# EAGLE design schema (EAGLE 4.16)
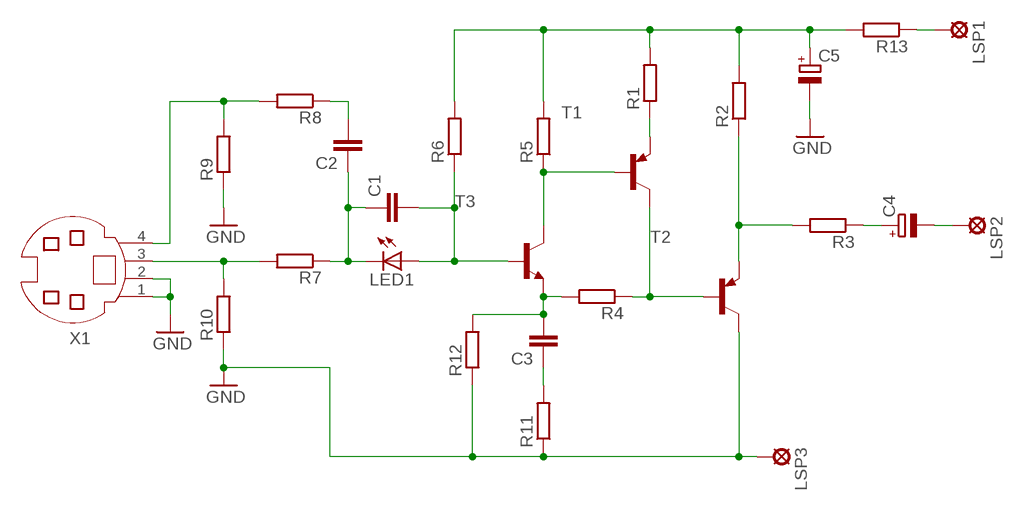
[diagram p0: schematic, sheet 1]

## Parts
C1  C-EU025-030X050  [C025-030X050]
C2  C-EU025-030X050  [C025-030X050]
C3  C-EU025-030X050  [C025-030X050]
C4  CPOL-EUSANYO_C  [SANYO-OSCON_C]
C5  CPOL-EUSANYO_C  [SANYO-OSCON_C]
LED1  LED5MM  [LED5MM]
LSP1  LSP11  [LSP11]
LSP2  LSP11  [LSP11]
LSP3  LSP11  [LSP11]
R1  R-EU_0204/7  [0204/7]
R2  R-EU_0204/7  [0204/7]
R3  R-EU_0204/7  [0204/7]
R4  R-EU_0204/7  [0204/7]
R5  R-EU_0204/7  [0204/7]
R6  R-EU_0204/7  [0204/7]
R7  R-EU_0204/7  [0204/7]
R8  R-EU_0204/7  [0204/7]
R9  R-EU_0204/7  [0204/7]
R10  R-EU_0204/7  [0204/7]
R11  R-EU_0204/7  [0204/7]
R12  R-EU_0204/7  [0204/7]
R13  R-EU_0204/7  [0204/7]
T1  BF421-PNP-TO92-BCE  [TO92-BCE]
T2  BF421-PNP-TO92-BCE  [TO92-BCE]
T3  BF199-NPN-TO92-BEC  [TO92-BEC]
X1  MD04S  [MDIN04S]

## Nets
GND: C5.- LSP3.MP R9.1 R10.1 R11.1 R12.1 T2.C X1.1 X1.2
N$1: R4.1 T1.C T2.B
N$2: R1.1 T1.E
N$3: R2.1 R3.2 T2.E
N$4: C3.2 R4.2 R12.2 T3.E
N$5: R5.1 T1.B T3.C
N$6: C5.+ R1.2 R2.2 R5.2 R6.2 R13.2
N$8: C1.2 LED1.A R6.1 T3.B
N$9: C1.1 C2.1 LED1.K(C) R7.1
N$10: C2.2 R8.1
N$11: R7.2 R10.2 X1.3
N$12: R8.2 R9.2 X1.4
N$13: C3.1 R11.2
N$16: C4.+ R3.1
N$17: LSP1.MP R13.1
N$18: C4.- LSP2.MP

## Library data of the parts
C1-C3 = rcl:C-EU: CAPACITOR, European symbol
C4 C5 = rcl:CPOL-EU: POLARIZED CAPACITOR, European symbol
LED1 = led:LED: LED
LSP1-LSP3 = solpad:LSP11: SOLDER PAD
R1-R13 = rcl:R-EU_: RESISTOR, European symbol
T1 T2 = transistor:*-PNP-: PNP Transistror
T3 = transistor:*-NPN-: NPN Transistror
X1 = con-yamaichi:MD04S: YAMAICHI CONNECTOR

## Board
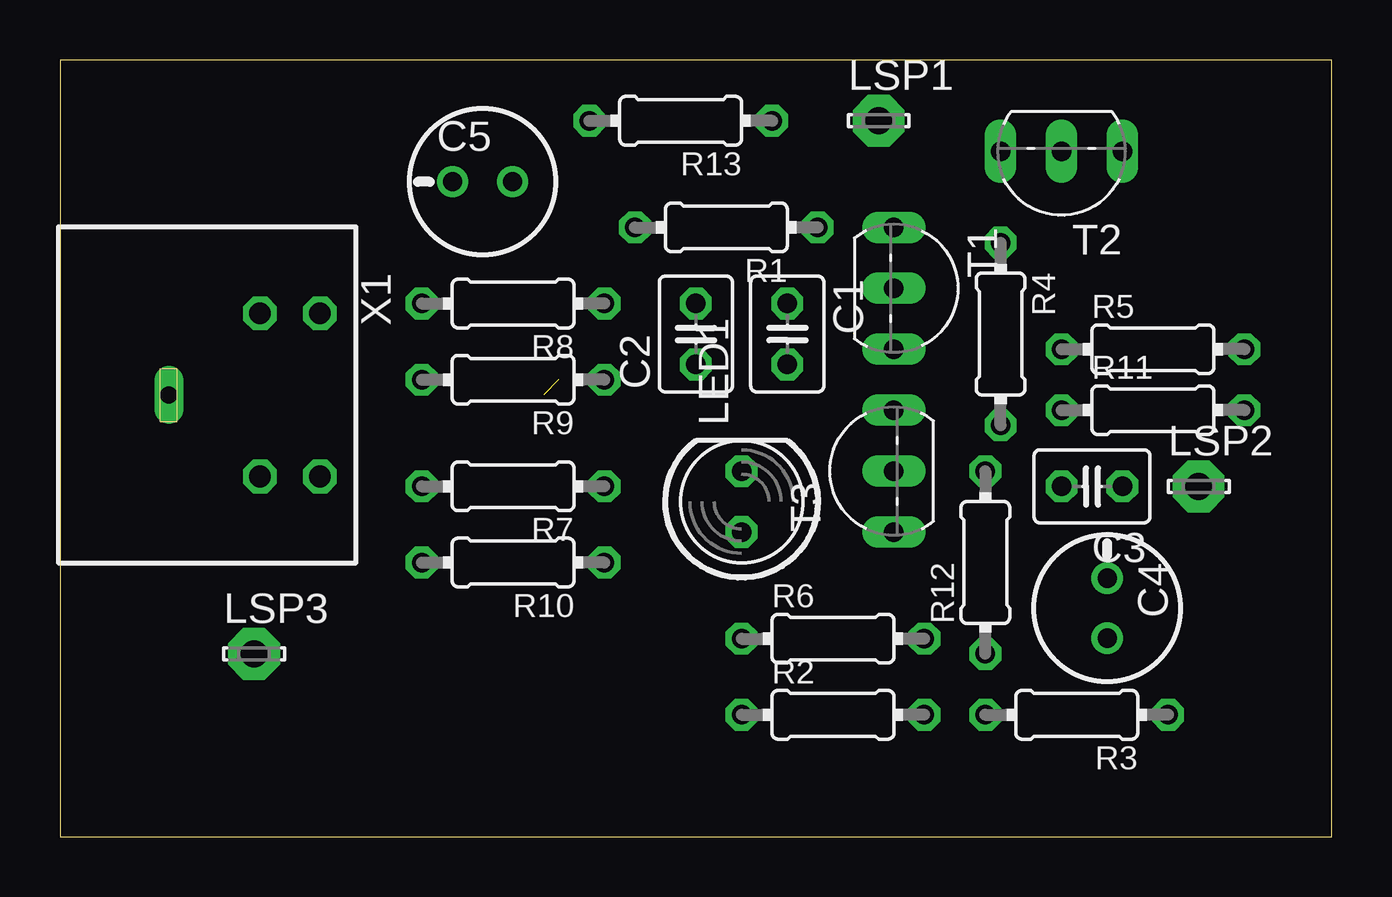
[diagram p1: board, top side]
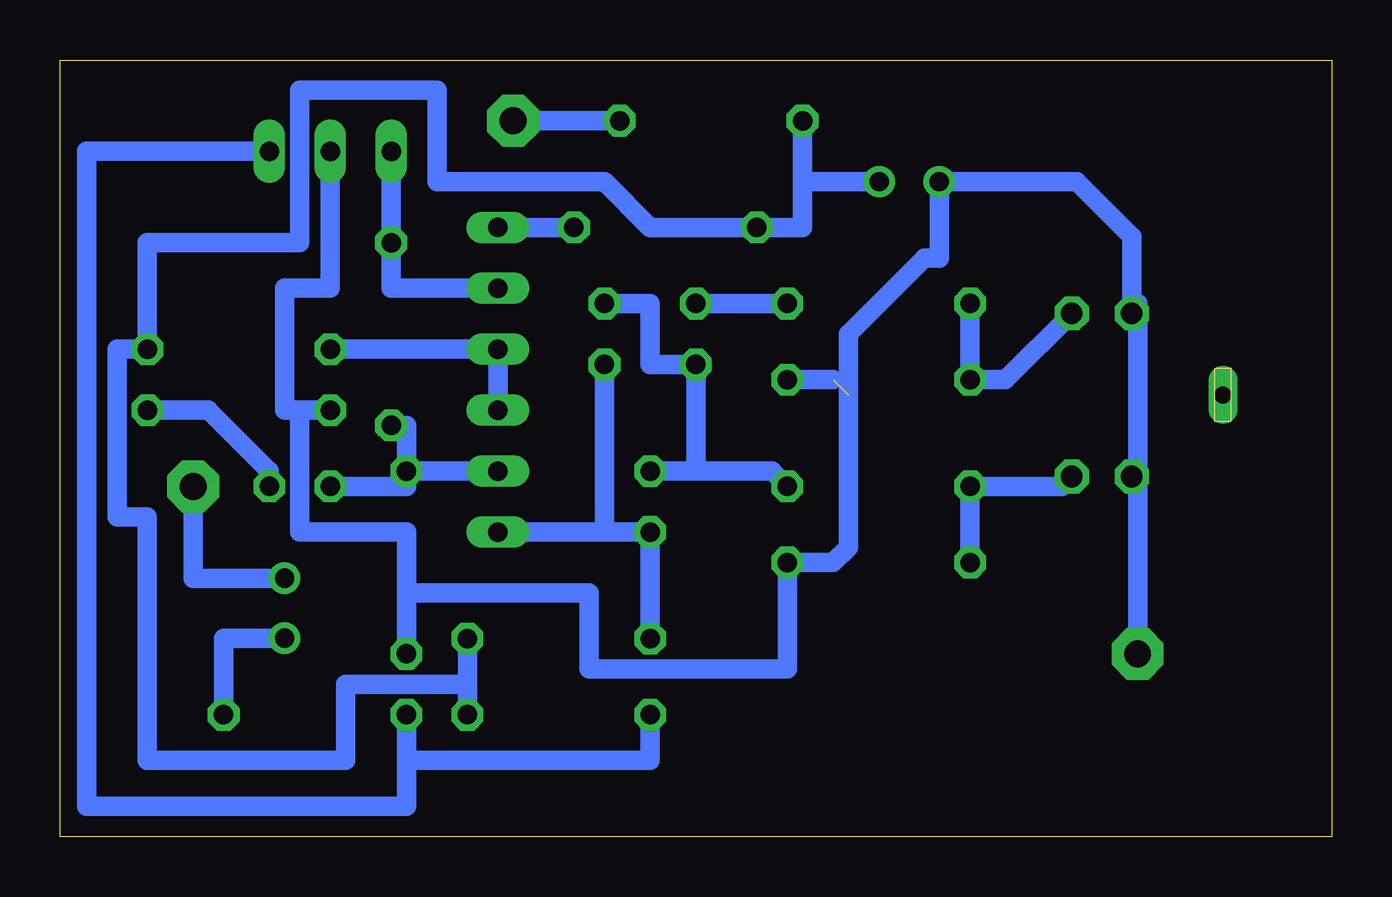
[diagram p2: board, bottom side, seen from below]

Size 53.01 x 32.38 mm. Coordinates in mm from the lower left corner, seen from the top.
Outline: 0,0 53.01,0 53.01,32.38 0,32.38 0,0
Copper layers (1*16): Top 0.035mm / dielectric 1.5mm / Bottom 0.035mm
Design rules "default": minimum track width 10mil, minimum drill 24mil, track to track 8mil, track to pad 8mil, pad to pad 8mil, via to via 8mil, smd to smd 8mil, copper to edge 40mil, drill to drill 8mil, minimum pad ring 10mil, minimum via ring 8mil, stop-mask expansion 4mil, vias tented up to drill 0mil, thermal gap 10mil

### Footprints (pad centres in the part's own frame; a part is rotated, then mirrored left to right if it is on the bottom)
C025-030X050 = drill 0.813 octagon: 1 -1.27,0; 2 1.27,0
SANYO-OSCON_C = drill 0.8 pad 1.27 round: + 1.25,0; - -1.25,0
LED5MM = drill 0.813 octagon: A -1.27,0; K 1.27,0
LSP11 = drill 1.118 pad 2.159 octagon: MP 0,0
0204/7 = drill 0.813 octagon: 1 -3.81,0; 2 3.81,0
TO92-BCE = drill 0.813 long: B 2.54,0; C 0,0; E -2.54,0
TO92-BEC = drill 0.813 long: B -2.54,0; C 2.54,0; E 0,0
MDIN04S = drill 0.9 octagon: 1 3.4,8.5; 2 -3.4,8.5; 3 3.4,11; 4 -3.4,11 | drill 0.7 long: M 0,4.7

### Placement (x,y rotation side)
C1  30.32,20.95 270 top
C2  26.51,20.95 90 top
C3  43.02,14.6 180 top
C4  43.65,9.52 270 top
C5  17.62,27.3 0 top
LED1  28.41,13.97 90 top
LSP1  34.12,29.84 0 top
LSP2  47.46,14.6 0 top
LSP3  8.09,7.62 0 top
R1  27.78,25.39 180 top
R2  32.22,5.08 0 top
R3  42.38,5.08 180 top
R4  39.2,20.95 270 top
R5  45.55,20.31 0 top
R6  32.22,8.25 0 top
R7  18.89,14.6 180 top
R8  18.89,22.22 180 top
R9  18.89,19.04 180 top
R10  18.89,11.43 180 top
R11  45.55,17.77 0 top
R12  38.57,11.43 90 top
R13  25.87,29.84 180 top
T1  34.76,22.86 270 top
T2  41.74,28.57 180 top
T3  34.76,15.24 90 top
X1  -0.17,18.41 270 top

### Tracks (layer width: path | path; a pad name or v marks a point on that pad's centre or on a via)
GND  (1 unrouted)
  Bottom 0.813: 8.09,21.81 8.09,22.22 | 8.09,21.81 X1.2 8.34,25 10.63,27.3 C5.- 16.35,27.3 16.35,24.12 16.98,24.12 20.16,20.95 20.16,18.41 20.16,12.06 20.79,11.43 R10.1 22.7,6.98 30.95,6.98 30.95,10.16 38.57,10.16 | 8.09,15.24 8.09,21.81 | 8.09,15.24 8.09,15.01 X1.1 | LSP3.MP 8.09,15.24 | 20.79,19.04 R9.1 | T2.C 41.74,22.86 43.65,22.86 43.65,17.77 R11.1 43.02,17.77 43.02,12.7 38.57,12.7 38.57,10.16 | 38.57,10.16 R12.1
N$1
  Bottom 0.813: T1.C 39.2,22.86 R4.1 T2.B
N$2
  Bottom 0.813: R1.1 T1.E
N$3
  Bottom 0.813: R2.1 28.41,3.17 38.57,3.17 | 38.57,3.17 R3.2 | T2.E 51.91,28.57 51.91,1.27 38.57,1.27 38.57,3.17
N$4
  Bottom 0.813: T3.E R12.2 | R12.2 38.57,17.14 R4.2 | C3.2 38.57,14.6 R12.2
N$5
  Bottom 0.813: T3.C T1.B R5.1
N$6
  Bottom 0.813: R2.2 36.03,6.34 | 36.03,6.34 R6.2 | 36.03,6.34 41.11,6.34 41.11,3.17 49.37,3.17 49.37,13.33 50.63,13.33 50.63,20.31 R5.2 49.37,24.76 43.02,24.76 43.02,31.11 37.3,31.11 37.3,27.3 30.32,27.3 28.41,25.39 R1.2 22.06,25.39 22.06,27.3 | 22.06,27.3 R13.2 | 22.06,27.3 C5.+
N$8
  Bottom 0.813: R6.1 LED1.A 30.32,12.7 | 30.32,12.7 C1.2 | 30.32,12.7 T3.B
N$9
  Bottom 0.813: R7.1 23.33,15.24 26.51,15.24 | 26.51,15.24 LED1.K | 26.51,15.24 C2.1 28.41,19.68 28.41,22.22 C1.1
N$10
  Bottom 0.813: R8.1 C2.2
N$11
  Bottom 0.813: X1.3 11.25,14.6 R7.2 R10.2
N$12
  Bottom 0.813: X1.4 13.6,19.04 R9.2 R8.2
N$13
  Bottom 0.813: C3.1 44.29,15.24 46.83,17.77 R11.2
N$16
  Bottom 0.813: C4.+ 46.19,8.27 R3.1
N$17
  Bottom 0.813: R13.1 LSP1.MP
N$18
  Bottom 0.813: C4.- 47.46,10.77 LSP2.MP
